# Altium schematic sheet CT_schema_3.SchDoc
size 283 x 174 mm
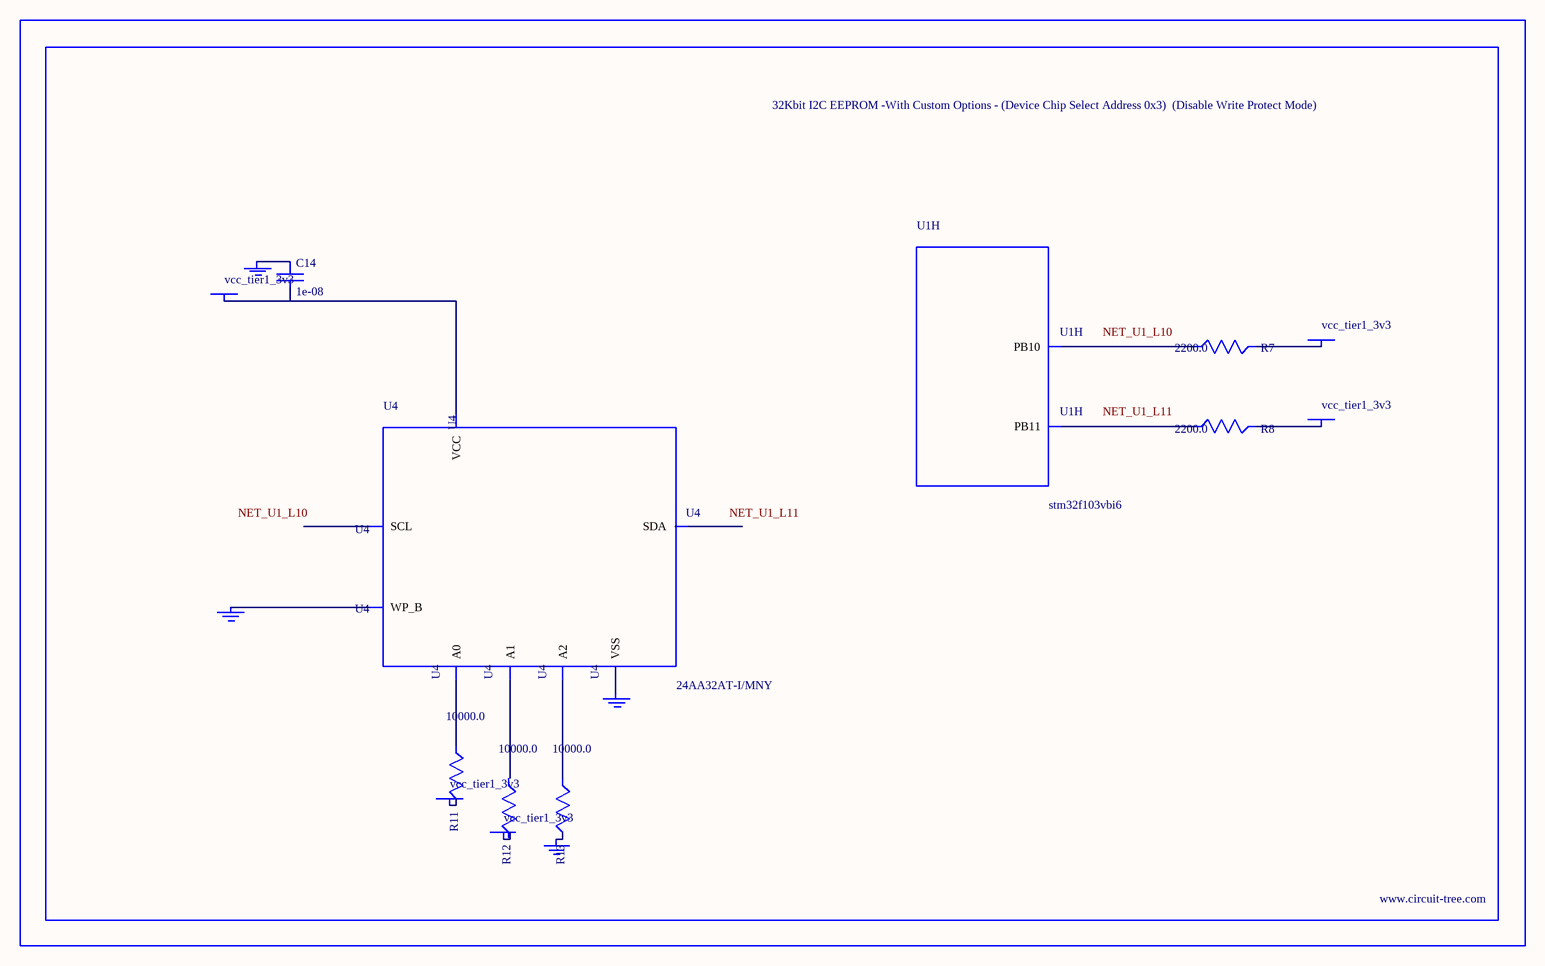
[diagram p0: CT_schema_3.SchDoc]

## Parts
BORDER2  (no value)
C14  1e-08  [C0402]
GND_INSTANCE_2_0  (no value)
GND_INSTANCE_2_1  (no value)
GND_INSTANCE_2_2  (no value)
GND_INSTANCE_2_3  (no value)
POWER_INSTANCE_2_0  vcc_tier1_3v3
POWER_INSTANCE_2_1  vcc_tier1_3v3
POWER_INSTANCE_2_2  vcc_tier1_3v3
POWER_INSTANCE_2_3  vcc_tier1_3v3
POWER_INSTANCE_2_4  vcc_tier1_3v3
R7  2200.0  [R0603]
R8  2200.0  [R0603]
R11  10000.0  [R0603]
R12  10000.0  [R0603]
R13  10000.0  [R0603]
U1  stm32f103vbi6  [UFBGA100]  (part H of 10)
U4  24AA32AT-I/MNY  [TDFN-8/6MM]

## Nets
NetC14_1: C14.1 GND_INSTANCE_2_2.0(GND)
NetC14_2: C14.2 POWER_INSTANCE_2_2.0(PWR) U4.8(VCC)
NetGND_INSTANCE_2_0_0: GND_INSTANCE_2_0.0(GND) R13.2
NetGND_INSTANCE_2_1_0: GND_INSTANCE_2_1.0(GND) U4.7(WP_B)
NetGND_INSTANCE_2_3_0: GND_INSTANCE_2_3.0(GND) U4.4(VSS)
NetPOWER_INSTANCE_2_0_0: POWER_INSTANCE_2_0.0(PWR) R11.2
NetPOWER_INSTANCE_2_3_0: POWER_INSTANCE_2_3.0(PWR) R7.2
NetPOWER_INSTANCE_2_4_0: POWER_INSTANCE_2_4.0(PWR) R8.2
NetR7_1: R7.1 U1.L10(PB10)
NetR8_1: R8.1 U1.L11(PB11)
NetR11_1: R11.1 U4.1(A0)
NetR13_1: R13.1 U4.3(A2)

Not connected (* = marked no-connect by the designer): POWER_INSTANCE_2_1 0(PWR); R12 1 2; U4 2(A1) 5(SDA) 6(SCL)

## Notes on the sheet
- Labels drawn without touching a wire or pin: NET_U1_L10, NET_U1_L11

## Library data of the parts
BORDER2 = BORDER_PAGE2
C14 = C0402C103K3RAC
GND_INSTANCE_2_0-GND_INSTANCE_2_3 = GND
POWER_INSTANCE_2_0-POWER_INSTANCE_2_4 = PWR
R7 R8 = RC0603JR-072K2L
R11-R13 = RC0603JR-0710KL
